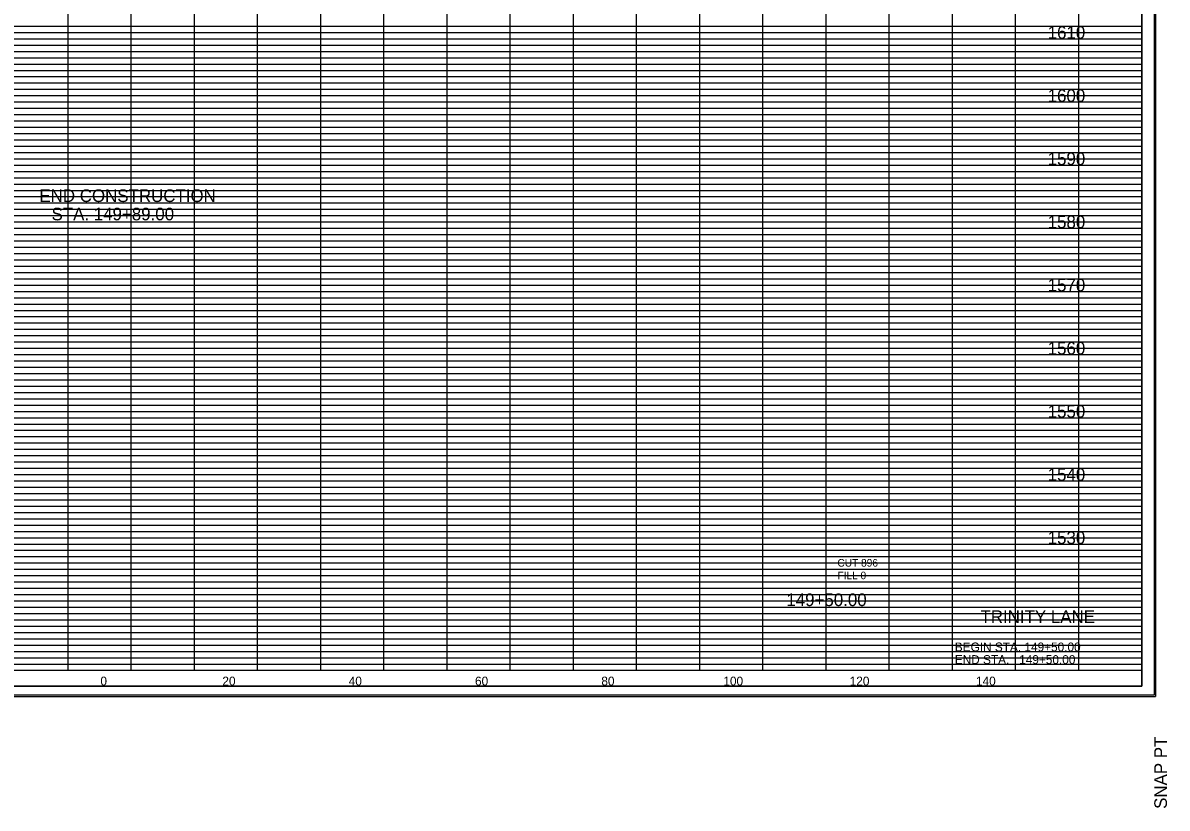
# Model space of a CAD drawing. Extents: x 980 to 1380, y 1248 to 3387.
# Drawn here: x 1142.8 to 1324, y 3138.2 to 3262.5 of the extents above; entities that cross this region are included whole.
import ezdxf

# ---------------------------------------------------------------- set-up
doc = ezdxf.new("R2010")
doc.units = 0
for name, color, linetype in [('DESIGN - SHEET - Corner Text', 7, 'Continuous'), ('DESIGN - SHEET - Light Grid', 7, 'Continuous'), ('DESIGN - SHEET - Linework', 7, 'Continuous'), ('DESIGN - SHEET - Plot Shape', 7, 'Continuous'), ('DESIGN - TYPICAL - Text', 7, 'Continuous')]:
    doc.layers.add(name, color=color, linetype=linetype)

# ---------------------------------------------------------------- blocks, each defined once
blk = doc.blocks.new('XSTSHT')
at = {"layer": 'DESIGN - SHEET - Light Grid'}
for p, q in [((8, 10.2), (16, 10.2)), ((16, 10.2), (24, 10.2)), ((24, 10.2), (32, 10.2)), ((8, 10.1), (16, 10.1)), ((16, 10.1), (24, 10.1)), ((24, 10.1), (32, 10.1)), ((8, 9.9), (16, 9.9)), ((8, 9.8), (16, 9.8)), ((16, 9.9), (24, 9.9)), ((16, 9.8), (24, 9.8)), ((24, 9.9), (32, 9.9)), ((24, 9.8), (32, 9.8)), ((8, 9.7), (16, 9.7)), ((16, 9.7), (24, 9.7)), ((24, 9.7), (32, 9.7)), ((8, 9.6), (16, 9.6)), ((8, 9.5), (16, 9.5)), ((16, 9.6), (24, 9.6)), ((16, 9.5), (24, 9.5)), ((24, 9.6), (32, 9.6)), ((24, 9.5), (32, 9.5)), ((8, 9.4), (16, 9.4)), ((8, 9.3), (16, 9.3)), ((16, 9.4), (24, 9.4)), ((16, 9.3), (24, 9.3)), ((24, 9.4), (32, 9.4)), ((24, 9.3), (32, 9.3)), ((8, 9.2), (16, 9.2)), ((8, 9.1), (16, 9.1)), ((16, 9.2), (24, 9.2)), ((16, 9.1), (24, 9.1)), ((24, 9.2), (32, 9.2)), ((24, 9.1), (32, 9.1)), ((8, 8.9), (16, 8.9)), ((16, 8.9), (24, 8.9)), ((24, 8.9), (32, 8.9)), ((8, 8.8), (16, 8.8)), ((8, 8.7), (16, 8.7)), ((16, 8.8), (24, 8.8)), ((16, 8.7), (24, 8.7)), ((24, 8.8), (32, 8.8)), ((24, 8.7), (32, 8.7)), ((8, 8.6), (16, 8.6)), ((16, 8.6), (24, 8.6)), ((24, 8.6), (32, 8.6)), ((8, 8.5), (16, 8.5)), ((8, 8.4), (16, 8.4)), ((16, 8.5), (24, 8.5)), ((16, 8.4), (24, 8.4)), ((24, 8.5), (32, 8.5)), ((24, 8.4), (32, 8.4)), ((8, 8.3), (16, 8.3)), ((8, 8.2), (16, 8.2)), ((16, 8.3), (24, 8.3)), ((16, 8.2), (24, 8.2)), ((24, 8.3), (32, 8.3)), ((24, 8.2), (32, 8.2)), ((8, 8.1), (16, 8.1)), ((16, 8.1), (24, 8.1)), ((24, 8.1), (32, 8.1)), ((8, 7.9), (16, 7.9)), ((8, 7.8), (16, 7.8)), ((16, 7.9), (24, 7.9)), ((16, 7.8), (24, 7.8)), ((24, 7.9), (32, 7.9)), ((24, 7.8), (32, 7.8)), ((8, 7.7), (16, 7.7)), ((16, 7.7), (24, 7.7)), ((24, 7.7), (32, 7.7)), ((8, 7.6), (16, 7.6)), ((8, 7.5), (16, 7.5)), ((16, 7.6), (24, 7.6)), ((16, 7.5), (24, 7.5)), ((24, 7.6), (32, 7.6)), ((24, 7.5), (32, 7.5)), ((8, 7.4), (16, 7.4)), ((8, 7.3), (16, 7.3)), ((16, 7.4), (24, 7.4)), ((16, 7.3), (24, 7.3)), ((24, 7.4), (32, 7.4)), ((24, 7.3), (32, 7.3)), ((8, 7.2), (16, 7.2)), ((8, 7.1), (16, 7.1)), ((16, 7.2), (24, 7.2)), ((16, 7.1), (24, 7.1)), ((24, 7.2), (32, 7.2)), ((24, 7.1), (32, 7.1)), ((8, 6.9), (16, 6.9)), ((16, 6.9), (24, 6.9)), ((24, 6.9), (32, 6.9)), ((8, 6.8), (16, 6.8)), ((16, 6.8), (24, 6.8)), ((24, 6.8), (32, 6.8)), ((8, 6.7), (16, 6.7)), ((8, 6.6), (16, 6.6)), ((16, 6.7), (24, 6.7)), ((16, 6.6), (24, 6.6)), ((24, 6.7), (32, 6.7)), ((24, 6.6), (32, 6.6)), ((8, 6.5), (16, 6.5)), ((8, 6.4), (16, 6.4)), ((16, 6.5), (24, 6.5)), ((16, 6.4), (24, 6.4)), ((24, 6.5), (32, 6.5)), ((24, 6.4), (32, 6.4)), ((8, 6.3), (16, 6.3)), ((8, 6.2), (16, 6.2)), ((16, 6.3), (24, 6.3)), ((16, 6.2), (24, 6.2)), ((24, 6.3), (32, 6.3)), ((24, 6.2), (32, 6.2)), ((8, 6.1), (16, 6.1)), ((16, 6.1), (24, 6.1)), ((24, 6.1), (32, 6.1)), ((8, 5.9), (16, 5.9)), ((8, 5.8), (16, 5.8)), ((16, 5.9), (24, 5.9)), ((16, 5.8), (24, 5.8)), ((24, 5.9), (32, 5.9)), ((24, 5.8), (32, 5.8)), ((8, 5.7), (16, 5.7)), ((16, 5.7), (24, 5.7)), ((24, 5.7), (32, 5.7)), ((8, 5.6), (16, 5.6)), ((8, 5.5), (16, 5.5)), ((16, 5.6), (24, 5.6)), ((16, 5.5), (24, 5.5)), ((24, 5.6), (32, 5.6)), ((24, 5.5), (32, 5.5)), ((8, 5.4), (16, 5.4)), ((8, 5.3), (16, 5.3)), ((16, 5.4), (24, 5.4)), ((16, 5.3), (24, 5.3)), ((24, 5.4), (32, 5.4)), ((24, 5.3), (32, 5.3)), ((8, 5.2), (16, 5.2)), ((8, 5.1), (16, 5.1)), ((16, 5.2), (24, 5.2)), ((16, 5.1), (24, 5.1)), ((24, 5.2), (32, 5.2)), ((24, 5.1), (32, 5.1)), ((8, 4.9), (16, 4.9)), ((16, 4.9), (24, 4.9)), ((24, 4.9), (32, 4.9)), ((8, 4.8), (16, 4.8)), ((16, 4.8), (24, 4.8)), ((24, 4.8), (32, 4.8)), ((8, 4.7), (16, 4.7)), ((8, 4.6), (16, 4.6)), ((16, 4.7), (24, 4.7)), ((16, 4.6), (24, 4.6)), ((24, 4.7), (32, 4.7)), ((24, 4.6), (32, 4.6)), ((8, 4.5), (16, 4.5)), ((8, 4.4), (16, 4.4)), ((16, 4.5), (24, 4.5)), ((16, 4.4), (24, 4.4)), ((24, 4.5), (32, 4.5)), ((24, 4.4), (32, 4.4)), ((8, 4.3), (16, 4.3)), ((8, 4.2), (16, 4.2)), ((16, 4.3), (24, 4.3)), ((16, 4.2), (24, 4.2)), ((24, 4.3), (32, 4.3)), ((24, 4.2), (32, 4.2)), ((8, 4.1), (16, 4.1)), ((16, 4.1), (24, 4.1)), ((24, 4.1), (32, 4.1)), ((8, 3.9), (16, 3.9)), ((16, 3.9), (24, 3.9)), ((24, 3.9), (32, 3.9)), ((8, 3.8), (16, 3.8)), ((8, 3.7), (16, 3.7)), ((16, 3.8), (24, 3.8)), ((16, 3.7), (24, 3.7)), ((24, 3.8), (32, 3.8)), ((24, 3.7), (32, 3.7)), ((8, 3.6), (16, 3.6)), ((8, 3.5), (16, 3.5)), ((16, 3.6), (24, 3.6)), ((16, 3.5), (24, 3.5)), ((24, 3.6), (32, 3.6)), ((24, 3.5), (32, 3.5)), ((8, 3.4), (16, 3.4)), ((8, 3.3), (16, 3.3)), ((16, 3.4), (24, 3.4)), ((16, 3.3), (24, 3.3)), ((24, 3.4), (32, 3.4)), ((24, 3.3), (32, 3.3)), ((8, 3.2), (16, 3.2)), ((8, 3.1), (16, 3.1)), ((16, 3.2), (24, 3.2)), ((16, 3.1), (24, 3.1)), ((24, 3.2), (32, 3.2)), ((24, 3.1), (32, 3.1)), ((8, 2.9), (16, 2.9)), ((16, 2.9), (24, 2.9)), ((24, 2.9), (32, 2.9)), ((8, 2.8), (16, 2.8)), ((16, 2.8), (24, 2.8)), ((24, 2.8), (32, 2.8)), ((8, 2.7), (16, 2.7)), ((8, 2.6), (16, 2.6)), ((16, 2.7), (24, 2.7)), ((16, 2.6), (24, 2.6)), ((24, 2.7), (32, 2.7)), ((24, 2.6), (32, 2.6)), ((8, 2.5), (16, 2.5)), ((8, 2.4), (16, 2.4)), ((16, 2.5), (24, 2.5)), ((16, 2.4), (24, 2.4)), ((24, 2.5), (32, 2.5)), ((24, 2.4), (32, 2.4)), ((8, 2.3), (16, 2.3)), ((8, 2.2), (16, 2.2)), ((16, 2.3), (24, 2.3)), ((16, 2.2), (24, 2.2)), ((24, 2.3), (32, 2.3)), ((24, 2.2), (32, 2.2)), ((8, 2.1), (16, 2.1)), ((16, 2.1), (24, 2.1)), ((24, 2.1), (32, 2.1)), ((8, 1.9), (16, 1.9)), ((16, 1.9), (24, 1.9)), ((24, 1.9), (32, 1.9)), ((8, 1.8), (16, 1.8)), ((8, 1.7), (16, 1.7)), ((16, 1.8), (24, 1.8)), ((16, 1.7), (24, 1.7)), ((24, 1.8), (32, 1.8)), ((24, 1.7), (32, 1.7)), ((8, 1.6), (16, 1.6)), ((8, 1.5), (16, 1.5)), ((16, 1.6), (24, 1.6)), ((16, 1.5), (24, 1.5)), ((24, 1.6), (32, 1.6)), ((24, 1.5), (32, 1.5)), ((8, 1.4), (16, 1.4)), ((8, 1.3), (16, 1.3)), ((16, 1.4), (24, 1.4)), ((16, 1.3), (24, 1.3)), ((24, 1.4), (32, 1.4)), ((24, 1.3), (32, 1.3)), ((8, 1.2), (16, 1.2)), ((8, 1.1), (16, 1.1)), ((16, 1.2), (24, 1.2)), ((16, 1.1), (24, 1.1)), ((24, 1.2), (32, 1.2)), ((24, 1.1), (32, 1.1)), ((8, 0.9), (16, 0.9)), ((8, 0.8), (16, 0.8)), ((16, 0.9), (24, 0.9)), ((16, 0.8), (24, 0.8)), ((24, 0.9), (32, 0.9)), ((24, 0.8), (32, 0.8)), ((8, 0.7), (16, 0.7)), ((8, 0.6), (16, 0.6)), ((16, 0.7), (24, 0.7)), ((16, 0.6), (24, 0.6)), ((24, 0.7), (32, 0.7)), ((24, 0.6), (32, 0.6)), ((8, 0.5), (16, 0.5)), ((8, 0.4), (16, 0.4)), ((16, 0.5), (24, 0.5)), ((16, 0.4), (24, 0.4)), ((24, 0.5), (32, 0.5)), ((24, 0.4), (32, 0.4)), ((8, 0.3), (16, 0.3)), ((8, 0.2), (16, 0.2)), ((16, 0.3), (24, 0.3)), ((16, 0.2), (24, 0.2)), ((24, 0.3), (32, 0.3)), ((24, 0.2), (32, 0.2)), ((8, 0.1), (16, 0.1)), ((16, 0.1), (24, 0.1)), ((24, 0.1), (32, 0.1))]:
    blk.add_line(p, q, dxfattribs=at)
at = {"layer": 'DESIGN - SHEET - Linework'}
for p, q in [((32.217, 21.414), (32.217, -0.414)), ((15, 0), (15, 21)), ((16, 0), (16, 21)), ((17, 0), (17, 21)), ((18, 0), (18, 21)), ((19, 0), (19, 21)), ((20, 0), (20, 21)), ((21, 0), (21, 21)), ((22, 0), (22, 21)), ((23, 0), (23, 21)), ((24, 0), (24, 21)), ((25, 0), (25, 21)), ((26, 0), (26, 21)), ((27, 0), (27, 21)), ((28, 0), (28, 20)), ((29, 0), (29, 20)), ((30, 0), (30, 20)), ((31, 0), (31, 20)), ((0, 10), (32, 10)), ((0, 9), (32, 9)), ((0, 8), (32, 8)), ((0, 7), (32, 7)), ((0, 6), (32, 6)), ((0, 5), (32, 5)), ((0, 4), (32, 4)), ((0, 3), (32, 3)), ((0, 2), (32, 2)), ((0, 1), (32, 1)), ((-1.823, -0.414), (32.217, -0.414))]:
    blk.add_line(p, q, dxfattribs=at)
blk.add_lwpolyline([(0, 21), (0, 0), (32, 0), (32, 21), (0, 21)], dxfattribs=at)
at = {"layer": 'DESIGN - SHEET - Plot Shape'}
for points in [[(-1.803, 21.394), (32.197, 21.394), (32.197, -0.394), (-1.803, -0.394)], [(-0.85, 21), (32, 21), (32, -0.25), (-0.85, -0.25)]]:
    blk.add_lwpolyline(points, close=True, dxfattribs=at)
at = {"layer": 'DESIGN - SHEET - Corner Text'}
blk.add_text('SNAP PT  ', height=0.2, rotation=90, dxfattribs=at).set_placement((32.397, -2.194))

msp = doc.modelspace()

# ---------------------------------------------------------------- linework, layer by layer
at = {"layer": 'DESIGN - SHEET - Plot Shape'}
msp.add_lwpolyline([(991.5, 3157.5), (1320, 3157.5), (1320, 3370), (991.5, 3370)], close=True, dxfattribs=at)

# ---------------------------------------------------------------- block references
at = {"layer": 'DESIGN - TYPICAL - Text', "xscale": 10, "yscale": 10}
msp.add_blockref('XSTSHT', (1000, 3160), dxfattribs=at)

# ---------------------------------------------------------------- texts
at = {"layer": 'DESIGN - SHEET - Corner Text'}
for s, height, p in [('TRINITY LANE', 2, (1294.45, 3167.5)), ('BEGIN STA. 149+50.00', 1.4, (1290.38, 3163)), ('END STA.   149+50.00', 1.4, (1290.38, 3161))]:
    msp.add_text(s, height=height, dxfattribs=at).set_placement(p)
at = {"layer": 'DESIGN - TYPICAL - Text'}
for s, height, p in [('     1610     ', 2, (1301.37, 3260)), ('     1600     ', 2, (1301.37, 3250)), ('     1590     ', 2, (1301.37, 3240)), ('END CONSTRUCTION', 2, (1145.45, 3234.15)), ('STA. 149+89.00', 2, (1147.37, 3231.25)), ('     1580     ', 2, (1301.37, 3230)), ('     1570     ', 2, (1301.37, 3220)), ('     1560     ', 2, (1301.37, 3210)), ('     1550     ', 2, (1301.37, 3200)), ('     1540     ', 2, (1301.37, 3190)), ('     1530     ', 2, (1301.37, 3180)), ('CUT 896', 1.2, (1271.8, 3176.42)), ('FILL 0', 1.2, (1271.8, 3174.42)), ('     149+50.00     ', 2, (1260, 3170.17)), ('     0     ', 1.4, (1152.51, 3157.6)), ('     0     ', 1.4, (1152.51, 3157.6)), ('     20     ', 1.4, (1171.82, 3157.6)), ('     40     ', 1.4, (1191.82, 3157.6)), ('     60     ', 1.4, (1211.82, 3157.6)), ('     80     ', 1.4, (1231.82, 3157.6)), ('     100     ', 1.4, (1251.14, 3157.6)), ('     120     ', 1.4, (1271.14, 3157.6)), ('     140     ', 1.4, (1291.14, 3157.6))]:
    msp.add_text(s, height=height, dxfattribs=at).set_placement(p)

doc.saveas('drawing.dxf')
